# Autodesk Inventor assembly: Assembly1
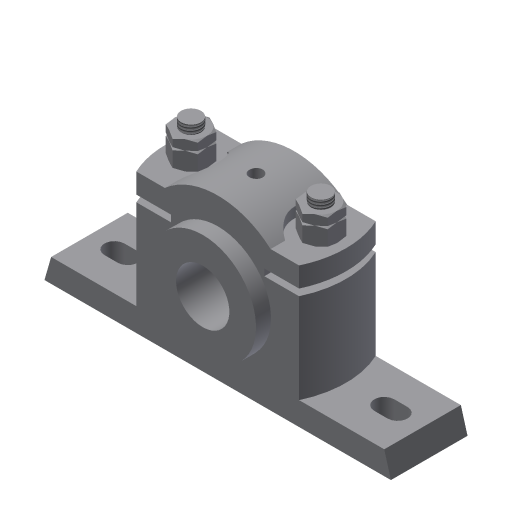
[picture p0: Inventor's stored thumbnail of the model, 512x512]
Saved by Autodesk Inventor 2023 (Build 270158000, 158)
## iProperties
Created: 2015-03
Part Number: Assembly1
Document SubType Name: Assembly
Designer: Sandeep
Author: Sandeep
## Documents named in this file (7)
- D:\PROJECTS\Project 2022\Autodesk Inventor For Professional 2023\RESOURCES INVENTOR 2023\RESOURCES INVENTOR 2023\Inventor_2023_tut\Inventor_2023_tut\c11_Inv_2023_tut\c11_Inv_tut_2023\c11_tut02_inv\Plummer Block.iam
- D:\PROJECTS\Project 2022\Autodesk Inventor For Professional 2023\RESOURCES INVENTOR 2023\RESOURCES INVENTOR 2023\Inventor_2023_tut\Inventor_2023_tut\c11_Inv_2023_tut\c11_Inv_tut_2023\c11_tut02_inv\Casting.ipt
- D:\PROJECTS\Project 2022\Autodesk Inventor For Professional 2023\RESOURCES INVENTOR 2023\RESOURCES INVENTOR 2023\Inventor_2023_tut\Inventor_2023_tut\c11_Inv_2023_tut\c11_Inv_tut_2023\c11_tut02_inv\Brasses.ipt
- D:\PROJECTS\Project 2022\Autodesk Inventor For Professional 2023\RESOURCES INVENTOR 2023\RESOURCES INVENTOR 2023\Inventor_2023_tut\Inventor_2023_tut\c11_Inv_2023_tut\c11_Inv_tut_2023\c11_tut02_inv\Cap.ipt
- D:\PROJECTS\Project 2022\Autodesk Inventor For Professional 2023\RESOURCES INVENTOR 2023\RESOURCES INVENTOR 2023\Inventor_2023_tut\Inventor_2023_tut\c11_Inv_2023_tut\c11_Inv_tut_2023\c11_tut02_inv\Bolt.ipt
- D:\PROJECTS\Project 2022\Autodesk Inventor For Professional 2023\RESOURCES INVENTOR 2023\RESOURCES INVENTOR 2023\Inventor_2023_tut\Inventor_2023_tut\c11_Inv_2023_tut\c11_Inv_tut_2023\c11_tut02_inv\Nut.ipt
- D:\PROJECTS\Project 2022\Autodesk Inventor For Professional 2023\RESOURCES INVENTOR 2023\RESOURCES INVENTOR 2023\Inventor_2023_tut\Inventor_2023_tut\c11_Inv_2023_tut\c11_Inv_tut_2023\c11_tut02_inv\locknut.ipt
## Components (9 placed, 6 different names)
1. Casting:1 — Mate:1, Mate:2, Insert:1, Insert:2, Angle:1, Angle:2
2. Brasses:1 — Mate:1, Mate:2, Mate:3, Mate:4
3. Cap:1 — Mate:3, Mate:4, Insert:3, Insert:4
4. Bolt:1 — Insert:1, Angle:2
5. Bolt:2 — Insert:2, Angle:1
6. Nut:1 — Insert:3, Insert:5
7. Nut:2 — Insert:4, Insert:6
8. locknut:1 — Insert:5
9. locknut:2 — Insert:6
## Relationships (12: Insert 6, Mate 4, Angle 2)
- Mate:1: Casting:1 ↔ Brasses:1
- Mate:2: Casting:1 ↔ Brasses:1
- Mate:3: Brasses:1 ↔ Cap:1
- Mate:4: Brasses:1 ↔ Cap:1
- Insert:1: Casting:1 ↔ Bolt:1
- Insert:2: Casting:1 ↔ Bolt:2
- Angle:1: Casting:1 ↔ Bolt:2
- Angle:2: Casting:1 ↔ Bolt:1
- Insert:3: Cap:1 ↔ Nut:1
- Insert:4: Cap:1 ↔ Nut:2
- Insert:5: Nut:1 ↔ locknut:1
- Insert:6: Nut:2 ↔ locknut:2
